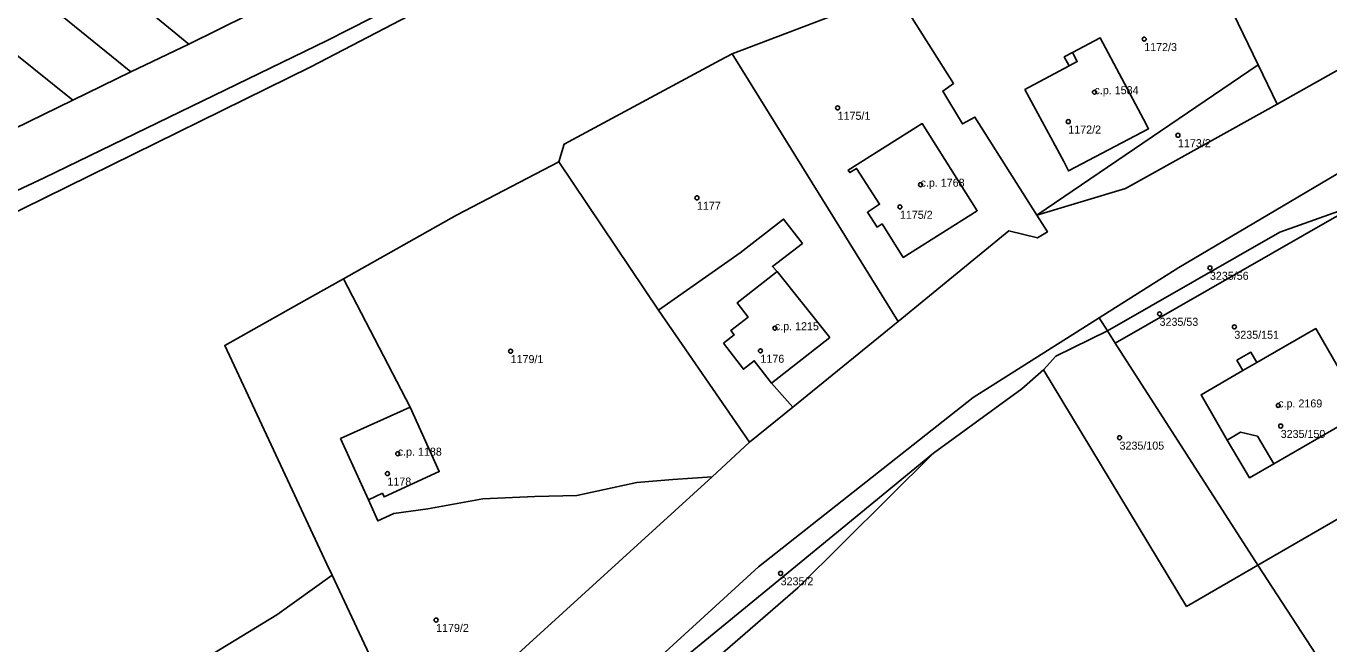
# Model space of a CAD drawing. Extents: x -878211 to -870363, y -1058464 to -1052522.
# Drawn here: x -875754.6 to -875591.8, y -1056545.8 to -1056468.6 of the extents above; entities that cross this region are included whole.
import ezdxf

# ---------------------------------------------------------------- set-up
doc = ezdxf.new("R2010")
doc.units = 0
for name, color, linetype in [('Definiční body', 7, 'Continuous'), ('Polygon budovy', 7, 'Continuous'), ('Polygon parcely', 7, 'Continuous')]:
    doc.layers.add(name, color=color, linetype=linetype)

msp = doc.modelspace()

# ---------------------------------------------------------------- linework, layer by layer
at = {"layer": 'Definiční body'}
for centre in [(-875614.92, -1056470.20994), (-875621.13, -1056476.83994), (-875653.22, -1056478.79994), (-875624.4, -1056480.51994), (-875610.7, -1056482.21994), (-875642.86, -1056488.39994), (-875670.79, -1056490.03994), (-875645.44, -1056491.16994), (-875606.71, -1056498.78994), (-875613, -1056504.53994), (-875661.06, -1056506.32994), (-875603.66, -1056506.15994), (-875694.07, -1056509.19994), (-875662.86, -1056509.15994), (-875598.18, -1056515.97994), (-875597.87, -1056518.54994), (-875618, -1056520.00994), (-875708.17, -1056522.00994), (-875709.46, -1056524.49994), (-875660.34, -1056536.95994), (-875703.38, -1056542.78994)]:
    msp.add_circle(centre, 0.25, dxfattribs=at)
at = {"layer": 'Polygon budovy'}
for points in [[(-875614.38, -1056481.4), (-875615, -1056480.23), (-875620.43, -1056470.04), (-875623.88, -1056471.88), (-875623.28, -1056473.01), (-875624.31, -1056473.56), (-875629.82, -1056476.52), (-875624.98, -1056485.51), (-875624.36, -1056486.67)], [(-875651.89, -1056486.58), (-875651.69, -1056486.89), (-875650.86, -1056486.36), (-875647.97, -1056490.85), (-875649.5, -1056491.83), (-875648.3, -1056493.69), (-875647.66, -1056493.29), (-875645.02, -1056497.49), (-875635.78, -1056491.66), (-875642.65, -1056480.76)], [(-875667.49, -1056508.21), (-875664.98, -1056511.45), (-875663.64, -1056510.4), (-875661.48, -1056513.19), (-875654.21, -1056507.47), (-875660.76, -1056499.25), (-875662.51, -1056500.62), (-875665.79, -1056503.17), (-875664.41, -1056504.94), (-875666.58, -1056506.62), (-875666.15, -1056507.17)], [(-875602.58, -1056511.63), (-875607.81, -1056514.65), (-875604.55, -1056520.3), (-875602.89, -1056519.32), (-875600.77, -1056519.82), (-875598.74, -1056523.29), (-875587.49, -1056516.78), (-875593.5, -1056506.38), (-875600.85, -1056510.63)], [(-875715.31, -1056520.12), (-875711.83, -1056527.78), (-875710.09, -1056526.95), (-875709.88, -1056527.4), (-875702.99, -1056524.25), (-875706.64, -1056516.18)]]:
    msp.add_lwpolyline(points, close=True, dxfattribs=at)
at = {"layer": 'Polygon parcely'}
for points in [[(-875798.29, -1056645.22), (-875745.74, -1056604.33), (-875700.24, -1056569.27), (-875697.39, -1056567.38), (-875687.84, -1056558.78), (-875663.09, -1056536.13), (-875636.28, -1056514.98), (-875620.56, -1056505.05), (-875610.6, -1056498.75), (-875590.01, -1056486.6), (-875573.69, -1056477.23), (-875574.76, -1056475.23), (-875566.36, -1056471.2), (-875559.09, -1056467.85), (-875549.25, -1056463.29), (-875536.95, -1056457.61), (-875520.18, -1056450), (-875504.56, -1056443.43), (-875473.56, -1056430.46), (-875458.61, -1056424.19), (-875420.94, -1056408.41), (-875385.5, -1056393.63)], [(-875781.56, -1056501.24), (-875752.35, -1056487.54), (-875717, -1056470.38), (-875683.67, -1056453.41), (-875690.35, -1056449.36), (-875696.67, -1056445.53), (-875671.55, -1056423.73), (-875668.4, -1056421.24), (-875665.19, -1056418.71), (-875667.46, -1056417.05), (-875672.6, -1056421.76), (-875678.32, -1056426.74), (-875684.66, -1056432.63), (-875690.22, -1056437.99), (-875696.35, -1056443.28), (-875701.98, -1056448.55), (-875707.54, -1056453.71), (-875713.43, -1056459), (-875719.97, -1056462.99), (-875726.86, -1056467.19), (-875734.26, -1056470.83), (-875741.5, -1056474.31), (-875748.75, -1056477.85), (-875756.09, -1056481.43)], [(-875759.48, -1056564.16), (-875723.29, -1056542.13), (-875716.38, -1056537.2), (-875717.03, -1056535.81), (-875729.78, -1056508.48), (-875719.88, -1056502.91), (-875714.95, -1056500.14), (-875700.83, -1056492.19), (-875688.06, -1056485.53), (-875687.4, -1056483.33), (-875667.88, -1056472.85), (-875666.38, -1056472.05), (-875646, -1056464.24), (-875647.35, -1056460.95), (-875657.28, -1056444.15), (-875682.29, -1056454.52), (-875719.03, -1056473.69), (-875779.94, -1056503.64)], [(-875568.53, -1056461.56), (-875598.32, -1056478.33), (-875617.25, -1056488.87), (-875628.33, -1056492.21), (-875627.01, -1056494.3), (-875628.26, -1056495.05), (-875631.83, -1056494.17), (-875645.67, -1056505.48), (-875658.83, -1056516.19), (-875664.23, -1056520.58), (-875668.91, -1056524.88), (-875706.22, -1056558.88)]]:
    msp.add_lwpolyline(points, dxfattribs=at)
for points in [[(-875568.53, -1056461.56), (-875558.91, -1056456.14), (-875559.82, -1056453.69), (-875574.31, -1056455.44), (-875583.46, -1056456.55), (-875592.06, -1056451.07), (-875601.1, -1056440.06), (-875574.64, -1056421.91), (-875575.1, -1056419.93), (-875586.9, -1056426.64), (-875593.3, -1056431.12), (-875612.19, -1056445.54), (-875612.59, -1056448.8), (-875613.76, -1056451.04), (-875611.4, -1056451.27), (-875600.7, -1056473.41), (-875598.32, -1056478.33)], [(-875734.26, -1056470.83), (-875726.86, -1056467.19), (-875769.82, -1056432.39), (-875772.89, -1056429.7), (-875773.22, -1056429.91), (-875771.66, -1056431.24), (-875774.26, -1056434.3), (-875776.74, -1056432.19), (-875779.34, -1056433.88)], [(-875779.34, -1056433.88), (-875785.98, -1056438.21), (-875741.5, -1056474.31), (-875734.26, -1056470.83)], [(-875741.5, -1056474.31), (-875785.98, -1056438.21), (-875792.66, -1056442.56), (-875748.75, -1056477.85)], [(-875794.15, -1056443.53), (-875799.46, -1056446.89), (-875756.09, -1056481.43), (-875748.75, -1056477.85), (-875792.66, -1056442.56)], [(-875616.97, -1056456.47), (-875630.79, -1056460.99), (-875640.22, -1056462.14), (-875646, -1056464.24), (-875638.73, -1056475.75), (-875640.09, -1056476.7), (-875637.61, -1056480.81), (-875636.07, -1056479.95), (-875628.33, -1056492.21), (-875600.7, -1056473.41), (-875611.4, -1056451.27), (-875613.76, -1056451.04)], [(-875779.94, -1056503.64), (-875719.03, -1056473.69), (-875682.29, -1056454.52), (-875683.67, -1056453.41), (-875717, -1056470.38), (-875752.35, -1056487.54), (-875781.56, -1056501.24), (-875819.27, -1056524.13)], [(-875628.33, -1056492.21), (-875636.07, -1056479.95), (-875637.61, -1056480.81), (-875640.09, -1056476.7), (-875638.73, -1056475.75), (-875646, -1056464.24), (-875666.38, -1056472.05), (-875645.67, -1056505.48), (-875631.83, -1056494.17), (-875628.26, -1056495.05), (-875627.01, -1056494.3)], [(-875620.43, -1056470.04), (-875623.88, -1056471.88), (-875624.91, -1056472.43), (-875624.31, -1056473.56), (-875629.82, -1056476.52), (-875624.98, -1056485.51), (-875624.36, -1056486.67), (-875614.38, -1056481.4), (-875615, -1056480.23)], [(-875620.43, -1056470.04), (-875615, -1056480.23), (-875614.38, -1056481.4), (-875624.36, -1056486.67), (-875624.98, -1056485.51), (-875629.82, -1056476.52), (-875624.31, -1056473.56), (-875624.91, -1056472.43), (-875623.88, -1056471.88)], [(-875675.61, -1056504.06), (-875665.41, -1056496.9), (-875659.98, -1056492.69), (-875657.62, -1056495.73), (-875661.36, -1056498.6), (-875660.76, -1056499.25), (-875654.21, -1056507.47), (-875661.48, -1056513.19), (-875658.83, -1056516.19), (-875645.67, -1056505.48), (-875666.38, -1056472.05), (-875667.88, -1056472.85), (-875687.4, -1056483.33), (-875688.06, -1056485.53)], [(-875628.33, -1056492.21), (-875617.25, -1056488.87), (-875598.32, -1056478.33), (-875600.7, -1056473.41)], [(-875645.02, -1056497.49), (-875635.78, -1056491.66), (-875642.65, -1056480.76), (-875651.89, -1056486.58), (-875651.69, -1056486.89), (-875650.86, -1056486.36), (-875647.97, -1056490.85), (-875649.5, -1056491.83), (-875648.3, -1056493.69), (-875647.66, -1056493.29)], [(-875645.02, -1056497.49), (-875647.66, -1056493.29), (-875648.3, -1056493.69), (-875649.5, -1056491.83), (-875647.97, -1056490.85), (-875650.86, -1056486.36), (-875651.69, -1056486.89), (-875651.89, -1056486.58), (-875642.65, -1056480.76), (-875635.78, -1056491.66)], [(-875664.23, -1056520.58), (-875675.61, -1056504.06), (-875688.06, -1056485.53), (-875700.83, -1056492.19), (-875714.95, -1056500.14), (-875706.64, -1056516.18), (-875702.99, -1056524.25), (-875709.88, -1056527.4), (-875710.09, -1056526.95), (-875711.83, -1056527.78), (-875710.68, -1056530.41), (-875708.68, -1056529.48), (-875704.4, -1056528.89), (-875697.54, -1056527.65), (-875691.05, -1056527.35), (-875685.81, -1056527.23), (-875681.38, -1056526.27), (-875678.32, -1056525.62), (-875673.8, -1056525.25), (-875668.91, -1056524.88)], [(-875620.56, -1056505.05), (-875619.51, -1056506.67), (-875597.99, -1056494.31), (-875587.58, -1056490.64), (-875590.01, -1056486.6), (-875610.6, -1056498.75)], [(-875591.14, -1056492.48), (-875587.58, -1056490.64), (-875597.99, -1056494.31), (-875619.51, -1056506.67), (-875618.53, -1056508.21)], [(-875587.58, -1056490.64), (-875591.14, -1056492.48), (-875618.53, -1056508.21), (-875600.74, -1056535.95), (-875570.74, -1056518.6), (-875573.95, -1056513.27), (-875585.55, -1056494.01)], [(-875664.23, -1056520.58), (-875658.83, -1056516.19), (-875661.48, -1056513.19), (-875654.21, -1056507.47), (-875660.76, -1056499.25), (-875661.36, -1056498.6), (-875657.62, -1056495.73), (-875659.98, -1056492.69), (-875665.41, -1056496.9), (-875675.61, -1056504.06)], [(-875711.83, -1056527.78), (-875715.31, -1056520.12), (-875706.64, -1056516.18), (-875714.95, -1056500.14), (-875719.88, -1056502.91), (-875729.78, -1056508.48), (-875717.03, -1056535.81), (-875716.38, -1056537.2), (-875706.22, -1056558.88), (-875668.91, -1056524.88), (-875673.8, -1056525.25), (-875678.32, -1056525.62), (-875681.38, -1056526.27), (-875685.81, -1056527.23), (-875691.05, -1056527.35), (-875697.54, -1056527.65), (-875704.4, -1056528.89), (-875708.68, -1056529.48), (-875710.68, -1056530.41)], [(-875663.09, -1056536.13), (-875687.84, -1056558.78), (-875697.39, -1056567.38), (-875700.24, -1056569.27), (-875699.05, -1056569.89), (-875682.26, -1056555.6), (-875661.73, -1056538.78), (-875641.25, -1056521.96), (-875630.21, -1056513.91), (-875627.5, -1056511.51), (-875625.96, -1056509.81), (-875619.51, -1056506.67), (-875620.56, -1056505.05), (-875636.28, -1056514.98)], [(-875618.53, -1056508.21), (-875619.51, -1056506.67), (-875625.96, -1056509.81), (-875627.5, -1056511.51), (-875609.62, -1056541.09), (-875600.74, -1056535.95)], [(-875602.58, -1056511.63), (-875607.81, -1056514.65), (-875604.55, -1056520.3), (-875601.78, -1056525.01), (-875598.74, -1056523.29), (-875587.49, -1056516.78), (-875593.5, -1056506.38), (-875600.85, -1056510.63), (-875601.6, -1056509.33), (-875603.33, -1056510.34)], [(-875602.58, -1056511.63), (-875603.33, -1056510.34), (-875601.6, -1056509.33), (-875600.85, -1056510.63), (-875593.5, -1056506.38), (-875587.49, -1056516.78), (-875598.74, -1056523.29), (-875601.78, -1056525.01), (-875604.55, -1056520.3), (-875607.81, -1056514.65)], [(-875544.46, -1056562.26), (-875551.66, -1056549.51), (-875581.32, -1056565.73), (-875600.74, -1056535.95), (-875609.62, -1056541.09), (-875627.5, -1056511.51), (-875630.21, -1056513.91), (-875641.25, -1056521.96), (-875658.21, -1056538.78), (-875679.47, -1056557.24), (-875687.91, -1056562.79), (-875699.05, -1056569.89), (-875698.51, -1056570.24), (-875682.5, -1056580.16), (-875670.11, -1056584.49), (-875572.4, -1056599.92), (-875540.37, -1056597.3), (-875525.37, -1056594.11), (-875525.81, -1056592.58), (-875539.84, -1056569.37)], [(-875702.99, -1056524.25), (-875706.64, -1056516.18), (-875715.31, -1056520.12), (-875711.83, -1056527.78), (-875710.09, -1056526.95), (-875709.88, -1056527.4)], [(-875600.74, -1056535.95), (-875581.32, -1056565.73), (-875551.66, -1056549.51), (-875560.46, -1056535.68), (-875570.74, -1056518.6)], [(-875658.21, -1056538.78), (-875641.25, -1056521.96), (-875661.73, -1056538.78), (-875682.26, -1056555.6), (-875699.05, -1056569.89), (-875687.91, -1056562.79), (-875679.47, -1056557.24)], [(-875804.7, -1056633.84), (-875768.34, -1056607.7), (-875706.22, -1056558.88), (-875716.38, -1056537.2), (-875723.29, -1056542.13), (-875759.48, -1056564.16), (-875765.09, -1056566.55), (-875759.62, -1056595.53), (-875758.73, -1056597.18), (-875788.49, -1056607.53), (-875818.6, -1056615.49), (-875835.53, -1056617.44), (-875829.12, -1056617.29), (-875820.9, -1056618.64), (-875814.51, -1056621.59), (-875808.87, -1056626.51), (-875804.7, -1056630.94)]]:
    msp.add_lwpolyline(points, close=True, dxfattribs=at)

# ---------------------------------------------------------------- texts
at = {"layer": 'Definiční body'}
for s, p in [('1172/3', (-875614.92, -1056471.699)), ('c.p. 1584', (-875621.13, -1056477.09)), ('1175/1', (-875653.22, -1056480.289)), ('1172/2', (-875624.4, -1056482.009)), ('1173/2', (-875610.7, -1056483.709)), ('c.p. 1768', (-875642.86, -1056488.649)), ('1177', (-875670.79, -1056491.529)), ('1175/2', (-875645.44, -1056492.659)), ('3235/56', (-875606.71, -1056500.279)), ('c.p. 1215', (-875661.06, -1056506.58)), ('3235/53', (-875613, -1056506.029)), ('3235/151', (-875603.66, -1056507.649)), ('1179/1', (-875694.07, -1056510.689)), ('1176', (-875662.86, -1056510.649)), ('c.p. 2169', (-875598.18, -1056516.23)), ('3235/150', (-875597.87, -1056520.039)), ('3235/105', (-875618, -1056521.499)), ('c.p. 1188', (-875708.17, -1056522.26)), ('1178', (-875709.46, -1056525.989)), ('3235/2', (-875660.34, -1056538.449)), ('1179/2', (-875703.38, -1056544.279))]:
    msp.add_text(s, height=0.999996, dxfattribs=at).set_placement(p)

doc.saveas('drawing.dxf')
